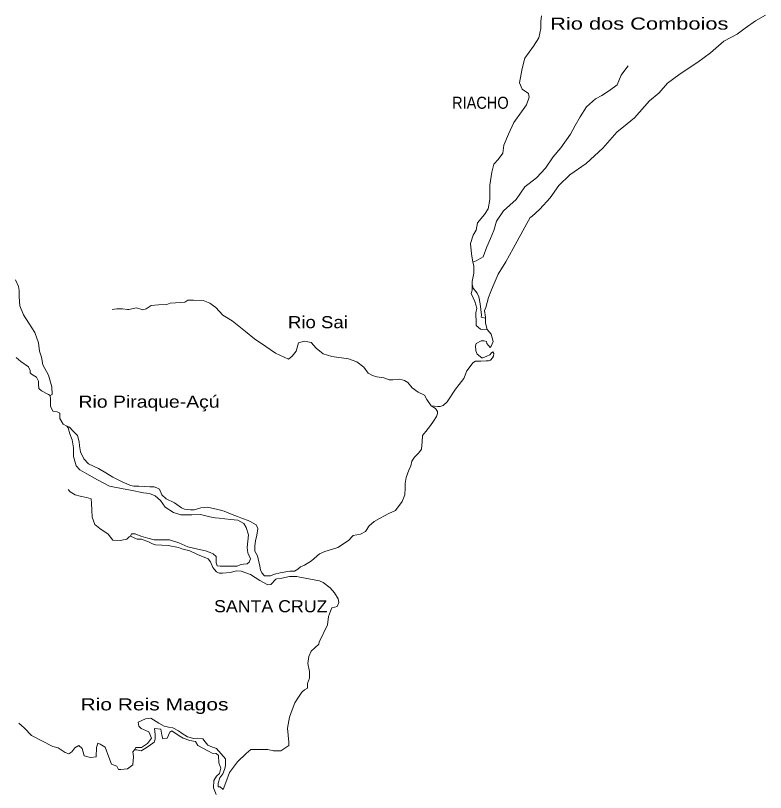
# Model space of a CAD drawing. Extents: x 47169 to 972804, y 7447977 to 9608469.
# Drawn here: x 364554 to 404488, y 7782191 to 7823571 of the extents above; entities that cross this region are included whole.
import ezdxf

# ---------------------------------------------------------------- set-up
doc = ezdxf.new("R2010")
doc.units = 0
doc.header["$LTSCALE"] = 270
doc.layers.add('1', color=7, linetype='Continuous', lineweight=13)
doc.layers.add('3', color=7, linetype='Continuous')

msp = doc.modelspace()

# ---------------------------------------------------------------- linework, layer by layer
at = {"layer": '1'}
for points in [[(383384.9, 7796395.6), (383655.6, 7796618.8), (383926.8, 7796775.5), (384197.9, 7796932.2), (384427.4, 7797055.5), (384792.7, 7797212.9), (385145.5, 7797691.1), (385289.9, 7798035.1), (385308.4, 7798400.5), (385296.4, 7798643.9), (385357.1, 7798965.3), (385490.6, 7799364.6), (385604.3, 7799586.7), (385655.1, 7799830.5), (385789.8, 7800041.7), (386029.1, 7800275.7), (386163.9, 7800475.8), (386203.2, 7800874.5), (386222.1, 7801195.6), (386409.2, 7801418.2), (386658.4, 7801740.7), (386814, 7801963.1), (386969.5, 7802218.7), (387031.3, 7802374), (387030.7, 7802473.6), (386924.8, 7802650), (386683.1, 7802781.3), (386871.7, 7802771.4), (387039.3, 7802750.4), (387165, 7802751.2), (387332.2, 7802796.5), (387529.9, 7802997), (387975.9, 7803675), (388183.8, 7803919.8), (388422.6, 7804242.3), (388587.7, 7804641.7), (388764.2, 7804875.3), (388899.1, 7805075.4), (389045.2, 7805153.8), (389338.4, 7805166.7), (389610.6, 7805179.4), (389736.3, 7805180.2), (389840.8, 7805214.1), (389955.2, 7805336.5), (390007.1, 7805425.4), (390016.6, 7805569.3), (389974.2, 7805657.6), (389890.7, 7805612.8), (389807.6, 7805501.6), (389651, 7805423.2), (389442.1, 7805333.3), (389379.3, 7805332.9), (389137.1, 7805530.6), (389073.1, 7805718.4), (389040.1, 7805972.7), (389081.2, 7806105.8), (389342.2, 7806240.3), (389509.7, 7806252.4), (389625.1, 7806208.8), (389657.2, 7806098.4), (389826.1, 7805889.1), (389878, 7805966.9), (389981.2, 7806211), (389884.5, 7806608.9), (389663, 7806851), (389587.6, 7807193.6), (389586, 7807448.2), (389585.6, 7807514.6), (389520.6, 7807857.3), (389603.4, 7808012.8), (389736.3, 7808544.8), (389870.4, 7808866.6), (389983.8, 7809166.2), (390252.2, 7809798.7), (390656.7, 7810454.2), (391060.9, 7811165), (391786.1, 7812497.6), (391962.3, 7812819.6), (392045.8, 7812864.4), (392473, 7813265.5), (393014.2, 7813866.4), (393492.2, 7814522.2), (394065.1, 7815090.1), (394941.8, 7815681.9), (395390, 7816094.1), (395827.7, 7816506.1), (396566.8, 7817351.6), (397119.6, 7817808.6), (397505.6, 7818120.7), (398307.4, 7819021.8), (398818.5, 7819456.3), (399266.3, 7819967.9), (399882.2, 7820414.1), (400425.1, 7820793.4), (400884.7, 7821083.8), (401563.2, 7821585.5), (402262.1, 7822209.2), (402972.9, 7822578.3), (403400.9, 7822901.5), (403954.4, 7823291.9), (404487.5, 7823582.5)], [(388862.4, 7809258.8), (388861.5, 7809402.7), (388963.4, 7809857.1), (388960.9, 7810244.4), (388896.8, 7810443.3), (388831.2, 7810885.6), (388775.4, 7811427.5), (388919.3, 7811871.2), (389074.8, 7812137.8), (389156.2, 7812525.6), (389530.6, 7812970.7), (389717.3, 7813281.8), (389808.5, 7813769.3), (389814.3, 7814533), (389914.7, 7815230.9), (390016.8, 7815663.2), (390245.9, 7815897), (390495.3, 7816241.7), (390555.6, 7816662.6), (390803.5, 7817250.7), (391082.6, 7817872.2), (391487.9, 7818450.2), (391758.1, 7818817.1), (391902.4, 7819216.4), (391869.7, 7819426.5), (391532.9, 7819656.9), (391394.6, 7819988), (391536.7, 7820752.6), (391680.1, 7821306.8), (392137.5, 7821940.5), (392428.3, 7822384.9), (392530.1, 7822883.6), (392527.9, 7823248.8), (392557.5, 7823558.9)], [(388896.8, 7810443.3), (389074.5, 7810510.8), (389450.3, 7810723.4), (389656.6, 7811244.9), (389852.8, 7811699.9), (390017.8, 7812121.5), (390171.9, 7812620.5), (390535.2, 7813165.1), (391212.5, 7813778), (391669.4, 7814455.9), (392295.3, 7814924.5), (392774.2, 7815436.5), (393189.7, 7816047.8), (393595.5, 7816526.1), (394104.6, 7817259.6), (394353.4, 7817714.9), (394623.1, 7818181.3), (394965.8, 7818714.6), (395435, 7819126.8), (395779.8, 7819317), (396187.1, 7819573.9), (396594, 7819886.2), (396800.7, 7820396.5), (397102.3, 7820807.7), (397175.2, 7820885.6)], [(366405.3, 7803325.7), (366499.1, 7803381.8), (366485.5, 7803791.2), (366302.8, 7804409.7), (366005.3, 7804971.9), (365939.3, 7805381), (365821.7, 7805701.1), (365776.4, 7806143.5), (365583.8, 7806684.4), (365255.3, 7807180), (364969, 7807631.6), (364776.8, 7808117.2), (364741.8, 7808581.8), (364739.2, 7808924.9), (364716.5, 7809146.1), (364553.6, 7809492.8)], [(389663, 7806851), (389317.3, 7806859.9), (389085.6, 7807068.8), (389083.9, 7807334.4), (389061.4, 7807588.8), (389060.4, 7807743.7), (389121.8, 7807976.5), (389014.8, 7808341.1), (388919.2, 7808539.7), (388813, 7808771.5), (388864.3, 7808948.9), (388862.4, 7809258.8), (388926.5, 7809048.9), (389137.7, 7808784.6), (389233.2, 7808586), (389298.4, 7808210.1), (389365, 7807612.8), (389344.7, 7807513.1), (389586, 7807448.2)], [(386683.1, 7802781.3), (386461.1, 7803111.9), (386323.5, 7803343.4), (385997.8, 7803507.4), (385682, 7803748.8), (385449.9, 7804024), (385260.7, 7804133.5), (385008.8, 7804209.3), (384642.5, 7804173.7), (384443.6, 7804172.4), (384170.6, 7804281.3), (383793.2, 7804334.2), (383562.4, 7804399), (383331.1, 7804530.3), (383098.7, 7804838.7), (382719.7, 7805135), (382289.3, 7805287.1), (381398.2, 7805414), (380936.4, 7805554.8), (380567.8, 7805851.1), (380303.9, 7806159.2), (379936.8, 7806234.2), (379612.8, 7806143.5), (379490.2, 7805688.9), (379282.5, 7805421.8), (379084.5, 7805276.6), (378401.6, 7805581.8), (377875.5, 7805943.4), (377286.1, 7806348.9), (376801.6, 7806743.9), (376443.5, 7807018.2), (376085.3, 7807314.5), (375590.9, 7807620.9), (375210.9, 7808027.8), (374905.5, 7808247), (374537.9, 7808388.3), (374024.4, 7808417.8), (373731.2, 7808404.7), (373564.3, 7808303.9), (373355, 7808280.2), (372789.6, 7808243), (372601.5, 7808175.2), (372172.1, 7808161.1), (371774.3, 7808125), (371503.2, 7807945.9), (371336.1, 7807889.4), (371000.1, 7807997.6), (370581.7, 7807917.1), (370508.4, 7807905.5), (370246.2, 7807947.8), (369952.9, 7807945.7), (369701.8, 7807910.6)], [(367286.8, 7801694.2), (367086.9, 7801814.4), (366906.7, 7802100.9), (366905.2, 7802300.1), (366904.5, 7802388.6), (366778.3, 7802465.2), (366547.7, 7802496.6), (366409.5, 7802772.3), (366406.7, 7803137.5), (366405.3, 7803325.7), (366310.6, 7803380.3), (365932.1, 7803576.7), (365794.9, 7803708.5), (365772.3, 7803929.7), (365781.5, 7804095.8), (365675.2, 7804305.3), (365401.6, 7804469.2), (365338.3, 7804535.2), (365337.3, 7804668), (365241.6, 7804855.4), (364841.4, 7805140.2), (364585.2, 7805365.7)], [(376992.1, 7794448.3), (377064.1, 7794637), (376925.8, 7794957), (376892.4, 7795244.5), (376960.9, 7795920.2), (376843.1, 7796295.7), (376705.5, 7796516.1), (376390.2, 7796691), (376002.7, 7796721.5), (375395, 7796794.6), (375185.4, 7796826.4), (374892, 7796868.5), (374409.6, 7796986.9), (373938.5, 7796983.5), (373352.3, 7796979.3), (372964, 7797109.3), (372522.3, 7797393.9), (372278.9, 7797746.3), (371984, 7797987.7), (371690, 7798107.3), (371375.6, 7798149.3), (370673.2, 7798288), (370190.9, 7798373), (369561.8, 7798501.2), (368910.2, 7798839.5), (368352.9, 7799156.4), (367984.8, 7799375), (367773.8, 7799594.8), (367644.5, 7800080.8), (367641, 7800545.7), (367575, 7800965.8), (367446.8, 7801296.9), (367350.3, 7801606.1), (367286.8, 7801694.2), (367423.2, 7801650.9), (367613.2, 7801453.1), (367855.9, 7801211.4), (367942.2, 7800868.9), (367954.2, 7800658.7), (368019.5, 7800338.2), (368189.8, 7799963.2), (368443.1, 7799699.4), (368978.9, 7799448.8), (369368.1, 7799208.2), (369725.8, 7798978.4), (370230.1, 7798738.6), (370471.7, 7798629.7), (370681.8, 7798531.6), (370849.6, 7798499.6), (371111.3, 7798501.6), (371404.5, 7798492.6), (371708.3, 7798472.7), (371928.2, 7798463.2), (372085.6, 7798420.1), (372222.2, 7798343.6), (372350.1, 7798034.6), (372582, 7797826), (373023.2, 7797618.9), (373391.5, 7797355.9), (373559.5, 7797279.6), (373873.8, 7797248.7), (374072.7, 7797250.1), (374417.4, 7797352.2), (374783.6, 7797388), (375328.8, 7797270.1), (375664.5, 7797172.9), (376094.9, 7796998.8), (376367.9, 7796890), (376640.8, 7796781.3), (376945.1, 7796683.8), (377039.8, 7796618), (377376, 7796443.3), (377450.6, 7796244.6), (377411.1, 7795901.2), (377329.5, 7795601.8), (377300, 7795324.9), (377291.5, 7795037), (377439.8, 7794794.5), (377569.2, 7794242), (377602, 7794054.1), (377676.4, 7793888.6), (377803, 7793734.5), (378138, 7793725.8), (378346.7, 7793815.8), (378649.7, 7793895.3), (379151.6, 7793976.3), (379413.2, 7793978.1), (379580, 7794078.8), (379736.1, 7794212.7), (379934.3, 7794302.6), (380309.6, 7794526.5), (380600.9, 7794783.1), (380736.2, 7794894.7), (381018, 7795018.4), (381425.4, 7795142.9), (381717.9, 7795233.4), (382291.1, 7795602.5), (382530.1, 7795869.7), (382916.8, 7795949.8), (383188.1, 7796084.4), (383384.9, 7796395.6)], [(370680.7, 7795841.9), (370597.2, 7795808.1), (370482.9, 7795685.5), (370117.1, 7795605.3), (369740.1, 7795635.8), (369486.5, 7795954.9), (369044.6, 7796250.4), (368770.8, 7796469.8), (368642.4, 7796845.2), (368608, 7797243.4), (368605.5, 7797575.4), (368582.7, 7797829.8), (368330.9, 7797894.4), (367995.3, 7797969.3), (367733, 7798044.8), (367470.2, 7798197.8), (367354, 7798329.8)], [(375454.7, 7782494.5), (375602.2, 7782351.6), (375746, 7782717.9), (375951.3, 7783261.7), (376365.8, 7783818.1), (376833.4, 7784264.1), (377083, 7784476.2), (377553.7, 7784479.5), (377815.2, 7784481.3), (377993, 7784482.6), (378286.5, 7784407.1), (378684, 7784409.9), (379100.5, 7784689.5), (379099.2, 7784877.7), (379041.8, 7785618.8), (379142.4, 7786195.1), (379286.2, 7786583.5), (379419.6, 7786960.7), (379585.3, 7787205.4), (379792.3, 7787538.9), (379948.4, 7787650.6), (380094.2, 7787751.2), (380103.9, 7787862), (380092.6, 7787994.7), (380205.8, 7788272.2), (380203.3, 7788637.4), (380127.2, 7789057.5), (380176.9, 7789434.2), (380300.5, 7789722.8), (380487.7, 7789890.1), (380706.1, 7790090.8), (380726.3, 7790190.6), (381159.6, 7791112.2), (381219.4, 7791555.3), (381332.5, 7791854.9), (381394.1, 7792021.4), (381561.3, 7792066.8), (381676.2, 7792089.7), (381769, 7792300.6), (381736.2, 7792510.7), (381545.7, 7792830.4), (381303.2, 7793094.4), (380935, 7793368.6), (380735.5, 7793466.9), (379687.5, 7793659), (379530.3, 7793691.1), (379143.1, 7793688.4), (378735.4, 7793608.1), (378474, 7793573.1), (378411.4, 7793550.5), (378141.2, 7793272), (377994.8, 7793248.8), (377564.1, 7793478.3), (377059.5, 7793795.7), (376576.7, 7793980.5), (376315, 7793989.7), (375980.7, 7793898.8), (375583.1, 7793873.9), (375405.2, 7793872.6), (375247.7, 7793949), (375057.6, 7794180.1), (374929.9, 7794478), (374803.2, 7794632.1), (374236.3, 7794860.5), (373826.7, 7795056.8), (373417.6, 7795175.6), (373228.8, 7795229.6), (372683.7, 7795336.3), (372338.1, 7795367), (372013.4, 7795386.8), (371908.5, 7795419.2), (371845.5, 7795440.9), (371625, 7795538.9), (371257.6, 7795680.1), (371027.2, 7795689.5), (370680.7, 7795841.9), (370732.1, 7795964.1), (370920.5, 7795965.4), (371225, 7795845.9), (371602.7, 7795726.9), (371938.2, 7795651.9), (372116.2, 7795653.2), (372388.3, 7795655.2), (372754.8, 7795646.7), (373247.8, 7795495.3), (373730.9, 7795277.5), (374098, 7795180.5), (374664.1, 7795062.8), (374915.9, 7794976), (375083.9, 7794899.7), (375241.9, 7794756.9), (375244.3, 7794424.9), (375297.8, 7794259.2), (375444.5, 7794238.2), (375884.1, 7794241.3), (376208.5, 7794243.6), (376355.1, 7794244.6), (376522.1, 7794312.2), (376699.8, 7794346.6), (376888, 7794370.1), (376992.1, 7794448.3)], [(375238, 7782083.4), (375099.5, 7782436.6), (375107.1, 7782835.1), (375252, 7783057.5), (375407.8, 7783202.5), (375489.5, 7783479.8), (375382.9, 7783766.8), (375359.1, 7784165.2), (375243.4, 7784263.9), (375023.5, 7784284.5), (374824, 7784382.7), (374267.3, 7784699.7), (374140.4, 7784898), (373836.5, 7784962.2), (373480, 7785081.4), (373269.8, 7785212.7), (372870.4, 7785475.5), (372766.2, 7785408.3), (372632.6, 7785075.3), (372392.2, 7785051.4), (372349, 7785239.2), (372283.9, 7785559.8), (371959.2, 7785601.7), (371982.6, 7785269.8), (371994.8, 7785026.4), (371943.7, 7784871), (371673.1, 7784669.8), (371412.8, 7784512.9), (371246.2, 7784401), (371005.2, 7784454.6), (370879.6, 7784464.7), (370962.4, 7784587.1), (371265.7, 7784589.3), (371588.6, 7784790.9), (371785.2, 7785080.2), (371646.7, 7785422.3), (371237.4, 7785596.4), (371110.9, 7785728.3), (371088.5, 7785927.3), (371474.3, 7786107.3), (371766.9, 7786153.7), (372187.4, 7785880), (372471, 7785727.2), (372701.5, 7785673.5), (372931.9, 7785642), (373226, 7785478.1), (373425.8, 7785335.6), (373709.6, 7785160.6), (374045, 7785063.4), (374254.1, 7785087), (374526.3, 7785055.8), (374642.6, 7784890.6), (374790.4, 7784703.5), (375042.1, 7784605.6), (375251.9, 7784529.7), (375726.6, 7783979.6), (375727.8, 7783802.5), (375729.2, 7783614.3), (375678.3, 7783414.8), (375585.8, 7783181.7), (375440.9, 7782970.3), (375338.2, 7782692.9), (375339.7, 7782482.6), (375454.7, 7782494.5)], [(370879.6, 7784464.7), (370807.2, 7784353.5), (370840.4, 7784099.2), (370801.8, 7783667.2), (370520.9, 7783454.8), (370155.1, 7783407.8), (370029.6, 7783406.9), (369944.6, 7783583.4), (369661.4, 7783691.9), (369522.6, 7784067.2), (369319.8, 7784608.1), (369057, 7784772.2), (368941.6, 7784815.6), (368870.1, 7784582.6), (368852.9, 7784084.4), (368549.8, 7784060), (368214.4, 7784134.9), (368106.8, 7784532.6), (367927.7, 7784697.3), (367709.1, 7784562.8), (367553.7, 7784362.4), (367397.6, 7784250.5), (367198.2, 7784326.5), (366830.3, 7784567.2), (366547.3, 7784631.4), (365402.5, 7785220.4), (365012.2, 7785626.9), (364735.1, 7785885.5)]]:
    msp.add_lwpolyline(points, dxfattribs=at)

# ---------------------------------------------------------------- texts
at = {"layer": '3'}
for s, height, width, p in [('Rio dos Comboios', 643.4, 1.35, (393024, 7822821.4)), ('RIACHO', 643.3, 0.9, (387801.6, 7818603.4)), ('Rio Sai', 642.9, 1.15, (379060.5, 7806918.5)), ('Rio Piraque-Açú', 642.8, 1.2, (367907.7, 7802684)), ('SANTA CRUZ', 642.3, 1.1, (375127, 7791789.8)), ('Rio Reis Magos', 642.2, 1.3, (368013.5, 7786562.7))]:
    msp.add_text(s, height=height, dxfattribs=dict(at, width=width)).set_placement(p)

doc.saveas('drawing.dxf')
